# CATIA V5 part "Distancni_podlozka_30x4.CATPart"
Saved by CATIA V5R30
Part number: Dosedaci_podlozka_30x4
Definition: E 1500_30x4_3
Nomenclature: E 1500_30x4_3
Source: Unknown
Description: PART--DESC
Bounding box of the stored display mesh (mm): x 189 to 219, y -105 to -75, z -224 to -220
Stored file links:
  E:\Bakalarka\Model\Forma_v7\Distancni_podlozka_30x4.CATPart
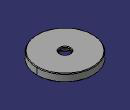
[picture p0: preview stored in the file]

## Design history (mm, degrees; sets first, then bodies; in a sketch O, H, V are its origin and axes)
Body1 "MANIFOLD_SOLID_BREP #4058" (main body)
  Solid1: solid without history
